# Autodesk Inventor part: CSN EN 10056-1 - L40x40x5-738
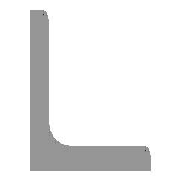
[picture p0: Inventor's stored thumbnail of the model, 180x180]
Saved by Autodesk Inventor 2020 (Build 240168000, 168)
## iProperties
Created: 2019-01
Part Number: CSN EN 10056-1 - L40x40x5-738
Material: Ocel, měkká
Description: Za tepla válcovaný konstrukcní ocelový profil - Rovnoramenné L2
Document SubType Name: Modeling
Standard: CSN EN 10056-1
Designer: doma
Standards Organization: CSN
Language: cs-CZ
Size Designation: L40x40x5-738
Categories: <MemberInstance><Categories><Category DisplayName="Konstrukční profily" InternalName="089c4875-fa83-4c05-b084-43b9cc11f5ed" Mnemonic="GRDR"><CategoryParameter D
Stock Number: L40x40x5
Density: 7.85 g/cm^3
Appearance: Pololeštěná
Mass: 2254.35 g
Surface Area: 1181.34 cm^2
Volume: 287.178 cm^3
G_L: 738,000 mm
IsCustomPart: 1
Author: doma
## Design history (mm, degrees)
node "Počáteční rovina"
node "Koncová rovina"
sketch "Náčrt2"
  geometry: L1 (-6.601, -0.601)-(-6.601, 25.399); L2 (-11.601, 28.399)-(-9.601, 28.399); L3 (-11.601, -11.601)-(-11.601, 28.399); L4 (-11.601, -11.601)-(28.399, -11.601); L5 (28.399, -9.601)-(28.399, -11.601); L6 (-0.601, -6.601)-(25.399, -6.601); L7 (0, 37.144)-(0, -19.726) reference; L8 (-19.726, 0)-(37.144, 0) reference; A1 r 6 centre (-0.601, -0.601) between (-6.601, -0.601) and (-0.601, -6.601); A2 r 3 centre (-9.601, 25.399) between (-6.601, 25.399) and (-9.601, 28.399); A3 r 3 centre (25.399, -9.601) between (28.399, -9.601) and (25.399, -6.601); 3 further points
  constraints: 12 end point, 6 point on circle, 6 point on line, 6 tangent, 3 centre point, 3 horizontal, 3 vertical, 1 equal radius
  dimensions: "d4" = 40 distance of L3.start L4.end (= b); "d6" = 40 distance of L3.start L2.start (= b); "d8" = 5 distance of point (28.399, -6.601) L4.end (= ParT); "d10" = 5 distance of L2.start point (-6.601, 28.399) (= ParT); "d17" = 6 radius of A1 (= R); "d18" = 3 radius of A2 (= R1); "d19" = 11.60131 distance between parallel lines of L8 L4 (= ex); "d20" = 11.60131 distance between parallel lines of L3 L7 (= d19)
extrude "Těleso" new body sketch "Náčrt2" stored distance "d11" = 758; taper "d12" = 0 deg
node "Driven Length"
  sketch "Sketch3"
    geometry: L1 (0, 0)-(10, 0) reference
    constraints: 2 end point, 1 horizontal
  workplane "Work Plane10"
  sketch "Sketch4"
    geometry: L1 (-2, 0)-(12, 0) reference; L2 (-2, 738)-(12, 738) reference
    dimensions: "d24" = 738 distance between parallel lines of L1 L2 (derived)
body "Solid1"
other parameters: "b" = 40 [user parameter; used in 3 equation terms], "ParT" = 5 [user parameter; used in 3 equation terms], "R" = 6 [user parameter; used in 1 equation term], "R1" = 3 [user parameter; used in 1 equation term], "G_L" = 738 (= d24) [user parameter], "d7" = 4 (derived), "d9" = 4 (derived), "ex" = 11.60131 (computed from b, ParT) [user parameter; used in 1 equation term], "G_OFFSET_START" = 0 [user parameter; used in 1 equation term], "G_OFFSET_END" = 0 [user parameter; used in 1 equation term], "d21" = 0 (computed from G_OFFSET_START), "d22" = 738 (= G_OFFSET_END + B_L), "B_L" = 738 [user parameter; used in 1 equation term], "d23" = 90 deg
